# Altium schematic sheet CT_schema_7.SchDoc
size 278 x 170 mm
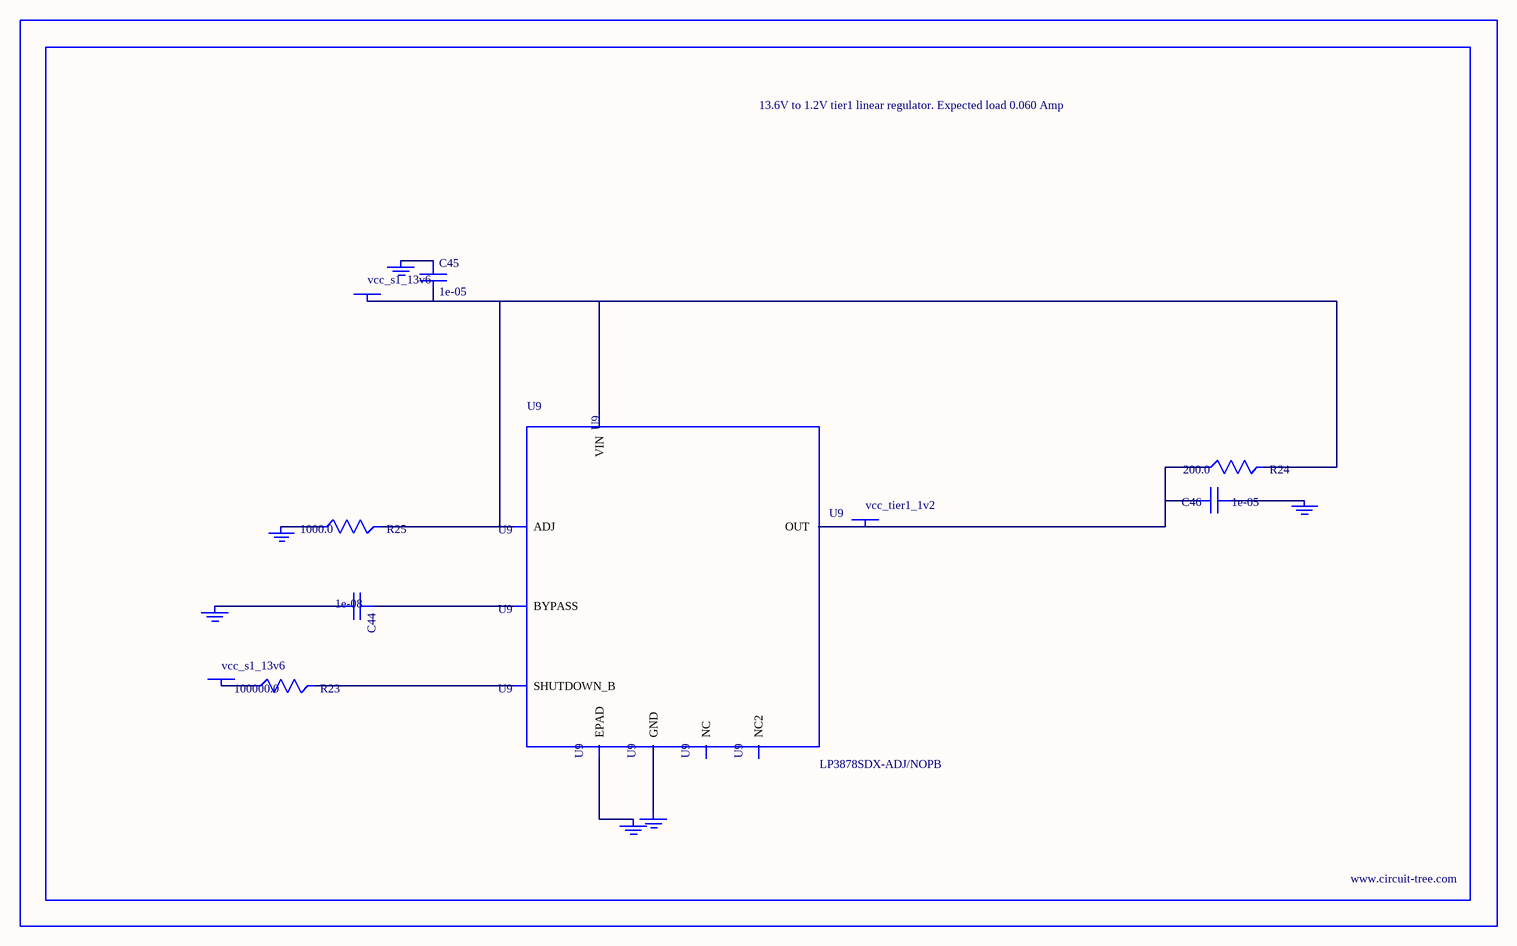
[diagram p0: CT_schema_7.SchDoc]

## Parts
BORDER6  (no value)
C44  1e-08  [C0402]
C45  1e-05  [C1210]
C46  1e-05  [C0805]
GND_INSTANCE_6_0  (no value)
GND_INSTANCE_6_1  (no value)
GND_INSTANCE_6_2  (no value)
GND_INSTANCE_6_3  (no value)
GND_INSTANCE_6_4  (no value)
GND_INSTANCE_6_5  (no value)
POWER_INSTANCE_6_0  vcc_s1_13v6
POWER_INSTANCE_6_1  vcc_s1_13v6
POWER_INSTANCE_6_2  vcc_tier1_1v2
R23  100000.0  [R0603]
R24  200.0  [R0603]
R25  1000.0  [R0603]
U9  LP3878SDX-ADJ/NOPB  [WSON-8]

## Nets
NetC44_1: C44.1 U9.1(BYPASS)
NetC44_2: C44.2 GND_INSTANCE_6_0.0(GND)
NetC45_1: C45.1 GND_INSTANCE_6_1.0(GND)
NetC45_2: C45.2 POWER_INSTANCE_6_0.0(PWR) R24.2 R25.2 U9.4(VIN) U9.6(ADJ)
NetC46_1: C46.1 GND_INSTANCE_6_2.0(GND)
NetC46_2: C46.2 POWER_INSTANCE_6_2.0(PWR) R24.1 U9.5(OUT)
NetGND_INSTANCE_6_3_0: GND_INSTANCE_6_3.0(GND) R25.1
NetGND_INSTANCE_6_4_0: GND_INSTANCE_6_4.0(GND) U9.PAD(EPAD)
NetGND_INSTANCE_6_5_0: GND_INSTANCE_6_5.0(GND) U9.3(GND)
NetPOWER_INSTANCE_6_1_0: POWER_INSTANCE_6_1.0(PWR) R23.1
NetR23_2: R23.2 U9.8(SHUTDOWN_B)

Not connected (* = marked no-connect by the designer): U9 2(NC) 7(NC2)

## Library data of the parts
BORDER6 = BORDER_PAGE6
C44 = C0402C103K3RAC
C45 = C1210C106K5PACTU
C46 = GRM219R60J106ME19D
GND_INSTANCE_6_0-GND_INSTANCE_6_5 = GND
POWER_INSTANCE_6_0-POWER_INSTANCE_6_2 = PWR
R23 = RC0603JR-07100KL
R24 = RC0603JR-07200RL
R25 = RC0603JR-071KL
